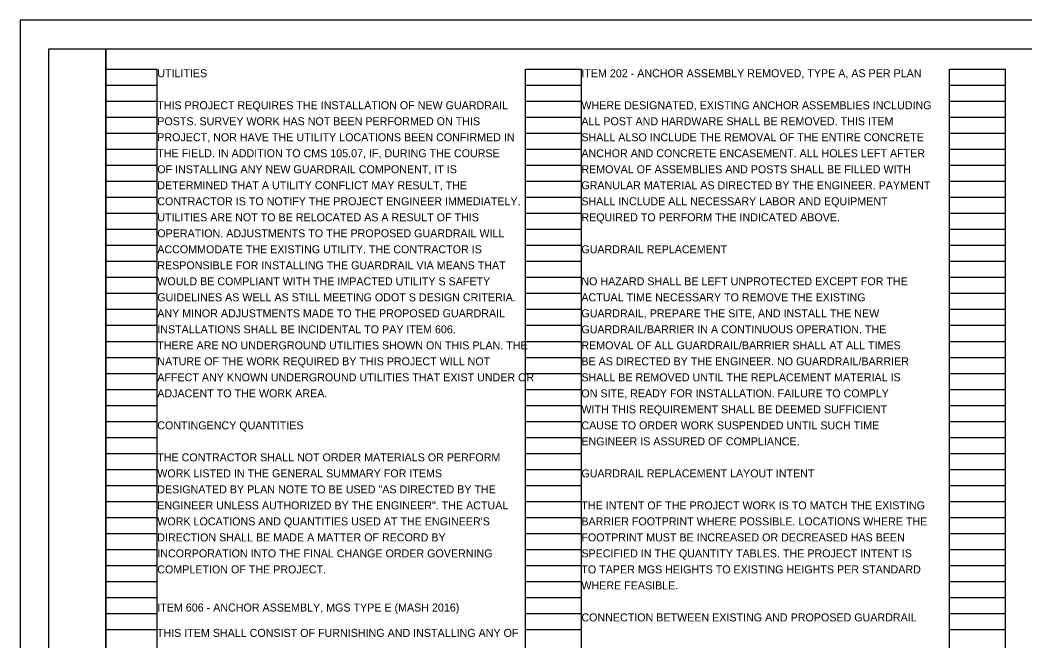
# Model space of a CAD drawing. Extents: x 0 to 34, y 0 to 22.
# Drawn here: x 0 to 17.58, y 11.14 to 22 of the extents above; entities that cross this region are included whole.
import ezdxf

# ---------------------------------------------------------------- set-up
doc = ezdxf.new("R2010")
doc.units = 0
for name, color, linetype in [('SH_Border', 7, 'Continuous'), ('SH_Cut_Line', 7, 'Continuous'), ('SH_Data', 7, 'Continuous'), ('SH_Text', 7, 'Continuous')]:
    doc.layers.add(name, color=color, linetype=linetype)

msp = doc.modelspace()

# ---------------------------------------------------------------- linework, layer by layer
at = {"layer": 'SH_Border'}
for points in [[(0.5, 21.5), (1.5, 21.5), (1.5, 0.5), (0.5, 0.5)], [(1.5, 21.5), (33.5, 21.5), (33.5, 0.5), (1.5, 0.5)]]:
    msp.add_lwpolyline(points, close=True, dxfattribs=at)
at = {"layer": 'SH_Cut_Line'}
msp.add_lwpolyline([(0, 0), (34, 0), (34, 22), (0, 22)], close=True, dxfattribs=at)
at = {"layer": 'SH_Data'}
for p, q in [((1.5, 0.98), (1.5, 21.14)), ((1.5, 21.14), (2.4, 21.14)), ((2.4, 0.98), (2.4, 21.14)), ((8.84, 0.98), (8.84, 21.14)), ((8.84, 21.14), (9.82, 21.14)), ((9.82, 0.98), (9.82, 21.14)), ((16.26, 0.98), (16.26, 21.14)), ((16.26, 21.14), (17.24, 21.14)), ((17.24, 0.98), (17.24, 21.14)), ((1.5, 20.86), (2.4, 20.86)), ((8.84, 20.86), (9.82, 20.86)), ((16.26, 20.86), (17.24, 20.86)), ((1.5, 20.58), (2.4, 20.58)), ((8.84, 20.58), (9.82, 20.58)), ((16.26, 20.58), (17.24, 20.58)), ((1.5, 20.3), (2.4, 20.3)), ((8.84, 20.3), (9.82, 20.3)), ((16.26, 20.3), (17.24, 20.3)), ((1.5, 20.02), (2.4, 20.02)), ((8.84, 20.02), (9.82, 20.02)), ((16.26, 20.02), (17.24, 20.02)), ((1.5, 19.74), (2.4, 19.74)), ((8.84, 19.74), (9.82, 19.74)), ((16.26, 19.74), (17.24, 19.74)), ((1.5, 19.46), (2.4, 19.46)), ((8.84, 19.46), (9.82, 19.46)), ((16.26, 19.46), (17.24, 19.46)), ((1.5, 19.18), (2.4, 19.18)), ((8.84, 19.18), (9.82, 19.18)), ((16.26, 19.18), (17.24, 19.18)), ((1.5, 18.9), (2.4, 18.9)), ((8.84, 18.9), (9.82, 18.9)), ((16.26, 18.9), (17.24, 18.9)), ((1.5, 18.62), (2.4, 18.62)), ((8.84, 18.62), (9.82, 18.62)), ((16.26, 18.62), (17.24, 18.62)), ((1.5, 18.34), (2.4, 18.34)), ((8.84, 18.34), (9.82, 18.34)), ((16.26, 18.34), (17.24, 18.34)), ((1.5, 18.06), (2.4, 18.06)), ((8.84, 18.06), (9.82, 18.06)), ((16.26, 18.06), (17.24, 18.06)), ((1.5, 17.78), (2.4, 17.78)), ((8.84, 17.78), (9.82, 17.78)), ((16.26, 17.78), (17.24, 17.78)), ((1.5, 17.5), (2.4, 17.5)), ((8.84, 17.5), (9.82, 17.5)), ((16.26, 17.5), (17.24, 17.5)), ((1.5, 17.22), (2.4, 17.22)), ((8.84, 17.22), (9.82, 17.22)), ((16.26, 17.22), (17.24, 17.22)), ((1.5, 16.94), (2.4, 16.94)), ((8.84, 16.94), (9.82, 16.94)), ((16.26, 16.94), (17.24, 16.94)), ((1.5, 16.66), (2.4, 16.66)), ((8.84, 16.66), (9.82, 16.66)), ((16.26, 16.66), (17.24, 16.66)), ((1.5, 16.38), (2.4, 16.38)), ((8.84, 16.38), (9.82, 16.38)), ((16.26, 16.38), (17.24, 16.38)), ((1.5, 16.1), (2.4, 16.1)), ((8.84, 16.1), (9.82, 16.1)), ((16.26, 16.1), (17.24, 16.1)), ((1.5, 15.82), (2.4, 15.82)), ((8.84, 15.82), (9.82, 15.82)), ((16.26, 15.82), (17.24, 15.82)), ((1.5, 15.54), (2.4, 15.54)), ((8.84, 15.54), (9.82, 15.54)), ((16.26, 15.54), (17.24, 15.54)), ((1.5, 15.26), (2.4, 15.26)), ((8.84, 15.26), (9.82, 15.26)), ((16.26, 15.26), (17.24, 15.26)), ((1.5, 14.98), (2.4, 14.98)), ((8.84, 14.98), (9.82, 14.98)), ((16.26, 14.98), (17.24, 14.98)), ((1.5, 14.7), (2.4, 14.7)), ((8.84, 14.7), (9.82, 14.7)), ((16.26, 14.7), (17.24, 14.7)), ((1.5, 14.42), (2.4, 14.42)), ((8.84, 14.42), (9.82, 14.42)), ((16.26, 14.42), (17.24, 14.42)), ((1.5, 14.14), (2.4, 14.14)), ((8.84, 14.14), (9.82, 14.14)), ((16.26, 14.14), (17.24, 14.14)), ((1.5, 13.86), (2.4, 13.86)), ((8.84, 13.86), (9.82, 13.86)), ((16.26, 13.86), (17.24, 13.86)), ((1.5, 13.58), (2.4, 13.58)), ((8.84, 13.58), (9.82, 13.58)), ((16.26, 13.58), (17.24, 13.58)), ((1.5, 13.3), (2.4, 13.3)), ((8.84, 13.3), (9.82, 13.3)), ((16.26, 13.3), (17.24, 13.3)), ((1.5, 13.02), (2.4, 13.02)), ((8.84, 13.02), (9.82, 13.02)), ((16.26, 13.02), (17.24, 13.02)), ((1.5, 12.74), (2.4, 12.74)), ((8.84, 12.74), (9.82, 12.74)), ((16.26, 12.74), (17.24, 12.74)), ((1.5, 12.46), (2.4, 12.46)), ((8.84, 12.46), (9.82, 12.46)), ((16.26, 12.46), (17.24, 12.46)), ((1.5, 12.18), (2.4, 12.18)), ((8.84, 12.18), (9.82, 12.18)), ((16.26, 12.18), (17.24, 12.18)), ((1.5, 11.9), (2.4, 11.9)), ((8.84, 11.9), (9.82, 11.9)), ((16.26, 11.9), (17.24, 11.9)), ((1.5, 11.62), (2.4, 11.62)), ((8.84, 11.62), (9.82, 11.62)), ((16.26, 11.62), (17.24, 11.62)), ((1.5, 11.34), (2.4, 11.34)), ((8.84, 11.34), (9.82, 11.34)), ((16.26, 11.34), (17.24, 11.34))]:
    msp.add_line(p, q, dxfattribs=at)

# ---------------------------------------------------------------- texts
at = {"layer": 'SH_Text'}
for s, p in [('UTILITIES', (2.4, 21)), ('ITEM 202 - ANCHOR ASSEMBLY REMOVED, TYPE A, AS PER PLAN', (9.82, 21)), ('THIS PROJECT REQUIRES THE INSTALLATION OF NEW GUARDRAIL', (2.4, 20.44)), ('WHERE DESIGNATED, EXISTING ANCHOR ASSEMBLIES INCLUDING', (9.82, 20.44)), ('POSTS. SURVEY WORK HAS NOT BEEN PERFORMED ON THIS', (2.4, 20.16)), ('ALL POST AND HARDWARE SHALL BE REMOVED. THIS ITEM', (9.82, 20.16)), ('PROJECT, NOR HAVE THE UTILITY LOCATIONS BEEN CONFIRMED IN', (2.4, 19.88)), ('SHALL ALSO INCLUDE THE REMOVAL OF THE ENTIRE CONCRETE', (9.82, 19.88)), ('THE FIELD. IN ADDITION TO CMS 105.07, IF, DURING THE COURSE', (2.4, 19.6)), ('ANCHOR AND CONCRETE ENCASEMENT. ALL HOLES LEFT AFTER', (9.82, 19.6)), ('OF INSTALLING ANY NEW GUARDRAIL COMPONENT, IT IS', (2.4, 19.32)), ('REMOVAL OF ASSEMBLIES AND POSTS SHALL BE FILLED WITH', (9.82, 19.32)), ('DETERMINED THAT A UTILITY CONFLICT MAY RESULT, THE', (2.4, 19.04)), ('GRANULAR MATERIAL AS DIRECTED BY THE ENGINEER. PAYMENT', (9.82, 19.04)), ('CONTRACTOR IS TO NOTIFY THE PROJECT ENGINEER IMMEDIATELY.', (2.4, 18.76)), ('SHALL INCLUDE ALL NECESSARY LABOR AND EQUIPMENT', (9.82, 18.76)), ('UTILITIES ARE NOT TO BE RELOCATED AS A RESULT OF THIS', (2.4, 18.48)), ('REQUIRED TO PERFORM THE INDICATED ABOVE.', (9.82, 18.48)), ('OPERATION. ADJUSTMENTS TO THE PROPOSED GUARDRAIL WILL', (2.4, 18.2)), ('ACCOMMODATE THE EXISTING UTILITY. THE CONTRACTOR IS', (2.4, 17.92)), ('GUARDRAIL REPLACEMENT', (9.82, 17.92)), ('RESPONSIBLE FOR INSTALLING THE GUARDRAIL VIA MEANS THAT', (2.4, 17.64)), ('WOULD BE COMPLIANT WITH THE IMPACTED UTILITY S SAFETY', (2.4, 17.36)), ('NO HAZARD SHALL BE LEFT UNPROTECTED EXCEPT FOR THE ', (9.82, 17.36)), ('GUIDELINES AS WELL AS STILL MEETING ODOT S DESIGN CRITERIA.', (2.4, 17.08)), ('ACTUAL TIME NECESSARY TO REMOVE THE EXISTING', (9.82, 17.08)), ('ANY MINOR ADJUSTMENTS MADE TO THE PROPOSED GUARDRAIL', (2.4, 16.8)), ('GUARDRAIL, PREPARE THE SITE, AND INSTALL THE NEW', (9.82, 16.8)), ('INSTALLATIONS SHALL BE INCIDENTAL TO PAY ITEM 606.', (2.4, 16.52)), ('GUARDRAIL/BARRIER IN A CONTINUOUS OPERATION. THE', (9.82, 16.52)), ('THERE ARE NO UNDERGROUND UTILITIES SHOWN ON THIS PLAN. THE', (2.4, 16.24)), ('REMOVAL OF ALL GUARDRAIL/BARRIER SHALL AT ALL TIMES ', (9.82, 16.24)), ('NATURE OF THE WORK REQUIRED BY THIS PROJECT WILL NOT', (2.4, 15.96)), ('BE AS DIRECTED BY THE ENGINEER. NO GUARDRAIL/BARRIER', (9.82, 15.96)), ('AFFECT ANY KNOWN UNDERGROUND UTILITIES THAT EXIST UNDER OR', (2.4, 15.68)), ('SHALL BE REMOVED UNTIL THE REPLACEMENT MATERIAL IS', (9.82, 15.68)), ('ADJACENT TO THE WORK AREA.', (2.4, 15.4)), ('ON SITE, READY FOR INSTALLATION. FAILURE TO COMPLY', (9.82, 15.4)), ('WITH THIS REQUIREMENT SHALL BE DEEMED SUFFICIENT', (9.82, 15.12)), ('CONTINGENCY QUANTITIES', (2.4, 14.84)), ('CAUSE TO ORDER WORK SUSPENDED UNTIL SUCH TIME', (9.82, 14.84)), ('ENGINEER IS ASSURED OF COMPLIANCE.', (9.82, 14.56)), ('THE CONTRACTOR SHALL NOT ORDER MATERIALS OR PERFORM', (2.4, 14.28)), ('WORK LISTED IN THE GENERAL SUMMARY FOR ITEMS', (2.4, 14)), ('GUARDRAIL REPLACEMENT LAYOUT INTENT', (9.82, 14)), ('DESIGNATED BY PLAN NOTE TO BE USED "AS DIRECTED BY THE', (2.4, 13.72)), ('ENGINEER UNLESS AUTHORIZED BY THE ENGINEER". THE ACTUAL', (2.4, 13.44)), ('THE INTENT OF THE PROJECT WORK IS TO MATCH THE EXISTING', (9.82, 13.44)), ("WORK LOCATIONS AND QUANTITIES USED AT THE ENGINEER'S", (2.4, 13.16)), ('BARRIER FOOTPRINT WHERE POSSIBLE. LOCATIONS WHERE THE', (9.82, 13.16)), ('DIRECTION SHALL BE MADE A MATTER OF RECORD BY', (2.4, 12.88)), ('FOOTPRINT MUST BE INCREASED OR DECREASED HAS BEEN', (9.82, 12.88)), ('INCORPORATION INTO THE FINAL CHANGE ORDER GOVERNING', (2.4, 12.6)), ('SPECIFIED IN THE QUANTITY TABLES. THE PROJECT INTENT IS', (9.82, 12.6)), ('COMPLETION OF THE PROJECT.', (2.4, 12.32)), ('TO TAPER MGS HEIGHTS TO EXISTING HEIGHTS PER STANDARD', (9.82, 12.32)), ('WHERE FEASIBLE.', (9.82, 12.04)), ('ITEM 606 - ANCHOR ASSEMBLY, MGS TYPE E (MASH 2016)', (2.4, 11.653)), ('CONNECTION BETWEEN EXISTING AND PROPOSED GUARDRAIL', (9.82, 11.48)), ('THIS ITEM SHALL CONSIST OF FURNISHING AND INSTALLING ANY OF ', (2.394, 11.209))]:
    msp.add_text(s, height=0.14, dxfattribs=at).set_placement(p)

doc.saveas('drawing.dxf')
